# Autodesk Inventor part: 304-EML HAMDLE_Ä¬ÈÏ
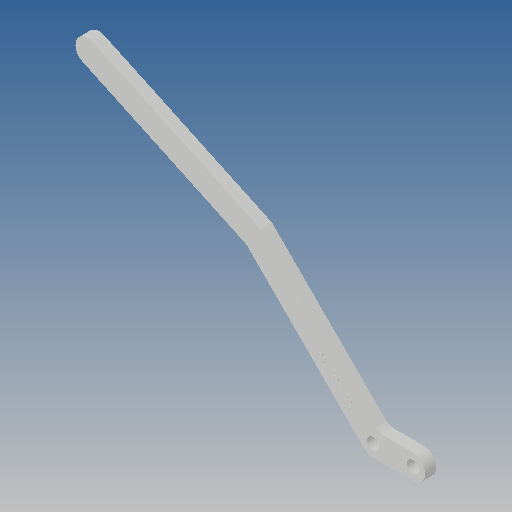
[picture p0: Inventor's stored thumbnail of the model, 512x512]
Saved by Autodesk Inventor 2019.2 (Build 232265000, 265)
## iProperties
Created: 2010-06
Part Number: 304-EML HAMDLE_Ä¬ÈÏ
Material: Ogólny
Document SubType Name: Modeling
Designer: CADENGINEERING4
Density: 1 g/cm^3
Appearance: Domyślna
Author: CADENGINEERING4
Revision Number: ÈÎºÎ
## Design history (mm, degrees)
feature "NONE"
node "Bryła1"
